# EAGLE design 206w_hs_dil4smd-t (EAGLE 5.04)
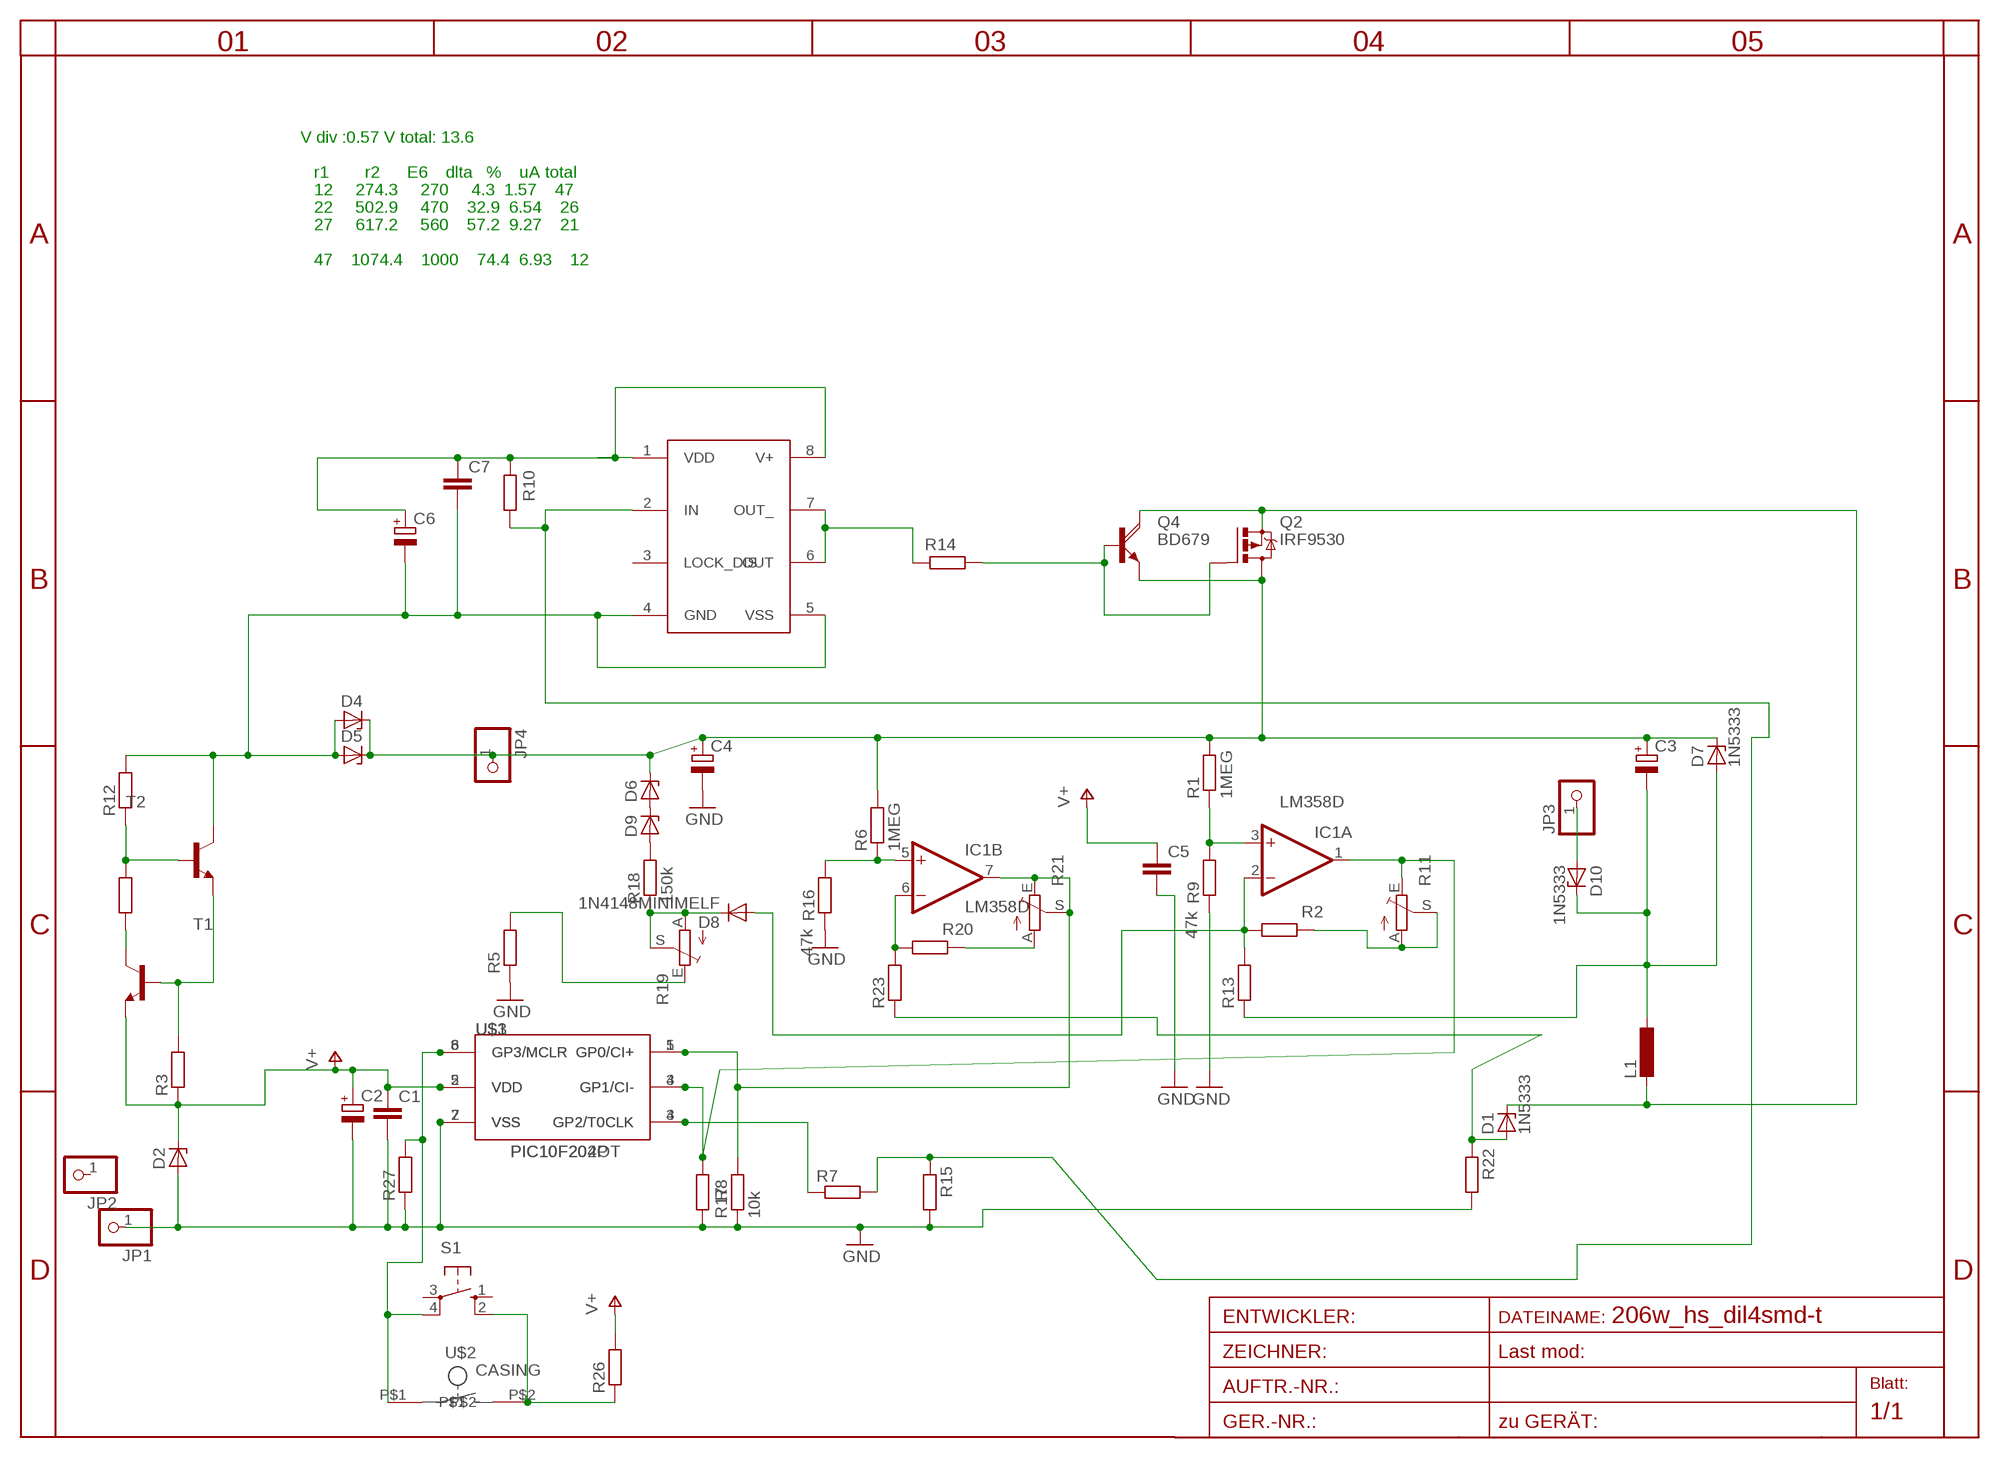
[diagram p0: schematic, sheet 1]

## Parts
C1  C-EUC1206  [C1206]
C2  CPOL-EUSANYO_SMD_E12  [SANYO-OSCON_SMD_E12]
C3  CPOL-EUE5-8.5  [E5-8,5]
C4  CPOL-EUE5-8.5  [E5-8,5]
C5  C-EUC1206  [C1206]
C6  CPOL-EUSANYO_SMD_E12  [SANYO-OSCON_SMD_E12]
C7  C-EUC1206  [C1206]
D1  1N5333  [C1702-15]
D2  ZENER-DIODESOT23  [SOT23]
D4  ZENER-DIODESMB  [SMB]
D5  ZENER-DIODESMB  [SMB]
D6  ZENER-DIODESMB  [SMB]
D7  1N5333  [C1702-15]
D8  1N4148MINIMELF  [MINIMELF]
D9  ZENER-DIODESMB  [SMB]
D10  1N5333  [C1702-15]
IC1  LM358D  [SO08]
IC3  TC4432X  [SO-08]
JP1  PINHD-1X1  [1X01]
JP2  PINHD-1X1  [1X01]
JP3  PINHD-1X1  [1X01]
JP4  PINHD-1X1  [1X01]
L1  L-EU2200-15.24  [2200-15.24]
Q2  IRF9530  [TO220BV]
Q4  BD679  [TO126AV]
R1  1MEG  R-EU_R1206  [R1206]
R2  R-EU_R0805  [R0805]
R3  R-EU_R0805  [R0805]
R5  R-EU_R0805  [R0805]
R6  1MEG  R-EU_R1206  [R1206]
R7  R-EU_R0805  [R0805]
R8  R-EU_R0805  [R0805]
R9  47k  R-EU_R0805  [R0805]
R10  R-EU_R0805  [R0805]
R11  TRIM_EU-CA6V  [CA6V]
R12  R-EU_R0805  [R0805]
R13  R-EU_R1206  [R1206]
R14  R-EU_0207/10  [0207/10]
R15  R-EU_R0805  [R0805]
R16  47k  R-EU_R0805  [R0805]
R17  10k  R-EU_R0805  [R0805]
R18  150k  R-EU_R1206  [R1206]
R19  TRIM_EU-CA6V  [CA6V]
R20  R-EU_R0805  [R0805]
R21  TRIM_EU-CA6V  [CA6V]
R22  R-EU_0309/12  [0309/12]
R23  R-EU_R1206  [R1206]
R24  R-EU_R0805  [R0805]
R26  R-EU_R0805  [R0805]
R27  R-EU_R0805  [R0805]
S1  10-XX  [B3F-10XX]
T1  BC846BLT1-NPN-SOT23-BEC  [SOT23-BEC]
T2  BC846BLT1-NPN-SOT23-BEC  [SOT23-BEC]
U$1  PIC10F202OT  [SOT23-6]
U$2  CASING  [CASING]
U$3  PIC10F204P  [DIL8]

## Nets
BB: IC3.2(IN) R7.2 R10.1 R15.1
EXIT: D10.A JP3.1
GND: C1.2 C2.- C4.- C5.2 D2.1(A) JP1.1 R5.1 R8.1 R9.1 R15.2 R16.1 R17.1 R22.2 R27.1 U$1.2(VSS) U$3.7(VSS)
HOT2: D1.A R22.1 R23.1
HOTSPOT: D1.C L1.2 Q4.C
N$1: R2.1 R11.A R11.S
N$2: IC1.1(A:OUT) R8.2 R11.E U$1.3(GP1/CI-) U$3.4(GP1/CI-)
N$3: R5.2 R19.E
N$4: D9.A R18.2
N$5: IC1.5(B:+IN) R6.1 R16.2
N$6: C6.- C7.2 D4.A D5.A IC3.4(GND) IC3.5(VSS) R12.2 T2.C
N$7: R27.2 S1.4(P1) U$1.6(GP3/MCLR) U$2.P$1 U$3.8(GP3/MCLR)
N$8: IC1.3(A:+IN) R1.1 R9.2
N$9: R7.1 U$1.4(GP2/T0CLK) U$3.3(GP2/T0CLK)
N$10: Q2.G Q4.B R14.1
N$11: IC3.6(OUT) IC3.7(OUT_) R14.2
N$12: R3.2 T1.B T2.E
N$13: D8.C R18.1 R19.A R19.S
N$14: IC1.7(B:OUT) R17.2 R21.E R21.S U$1.1(GP0/CI+) U$3.5(GP0/CI+)
N$15: D8.A IC1.2(A:-IN) R2.2 R13.2
N$17: R26.1 S1.2(S1) U$2.P$2
N$19: R24.1 T1.C
N$22: R12.1 R24.2 T2.B
N$23: D6.A D9.C
N$24: IC1.6(B:-IN) R20.2 R23.2
N$25: R20.1 R21.A
V60: C3.+ C4.+ D4.C D5.C D6.C D7.C JP4.1 Q2.D Q4.E R1.2 R6.2
V+: C1.1 C2.+ C5.1 D2.3(C) R3.1 R26.2 T1.E U$1.5(VDD) U$3.2(VDD)
VCC: C6.+ C7.1 IC3.1(VDD) IC3.8(V+) R10.2
VOUT: C3.- D7.A D10.C L1.1 R13.1
Unconnected: IC3.3(LOCK_DIS) JP2.1 Q2.S S1.1(S) S1.3(P)

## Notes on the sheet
- V div :0.57 V total: 13.6
- r1        r2      E6    dlta   %    uA total
- 12     274.3     270     4.3  1.57    47
- 22     502.9     470    32.9  6.54    26
- 27     617.2     560    57.2  9.27    21
- 47    1074.4    1000    74.4  6.93    12

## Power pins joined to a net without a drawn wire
GND: IC1.4(P:V-)
V+: IC1.8(P:V+)

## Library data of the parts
C1 C5 C7 = rcl:C-EU: CAPACITOR, European symbol
C2-C4 C6 = rcl:CPOL-EU: POLARIZED CAPACITOR, European symbol
D1 D7 D10 = diode-1:1N5333: Z DIODE
D2 D4-D6 D9 = diode-1:ZENER-DIODE: Z-Diode
D8 = diode-1:1N4148: DIODE
IC1 = linear4:LM358: OP AMP
IC3 = microchip:TC4432
JP1-JP4 = pinhead:PINHD-1X1: PIN HEADER
L1 = rcl:L-EU: INDUCTOR, European symbol
Q2 = transistor-power:IRF9530: P-CHANNEL HEXFET POWER-MOS-FET Source: http://www.irf.com/product-info/datasheets/data/irf9530.pdf
Q4 = transistor-power:BD679: NPN DARLINGTON TRANSISTOR
R1-R3 R5 R6 R8-R10 R12 R14-R16 R20 R24 R26 R27 = rcl:R-EU_: RESISTOR, European symbol
R7 R13 R17 R18 R22 R23 = rcl-2:R-EU_: RESISTOR, European symbol
R11 R19 R21 = pot:TRIM_EU-: POTENTIOMETER
S1 = switch-omron:10-XX: OMRON SWITCH
T1 T2 = transistor-neu-to92:*-NPN-: NPN Transistror
U$1 U$3 = microchip-5:PIC10F2*: uPC nW 0,25/0,5k Program Flash memory Comparator
U$2 = button:CASING

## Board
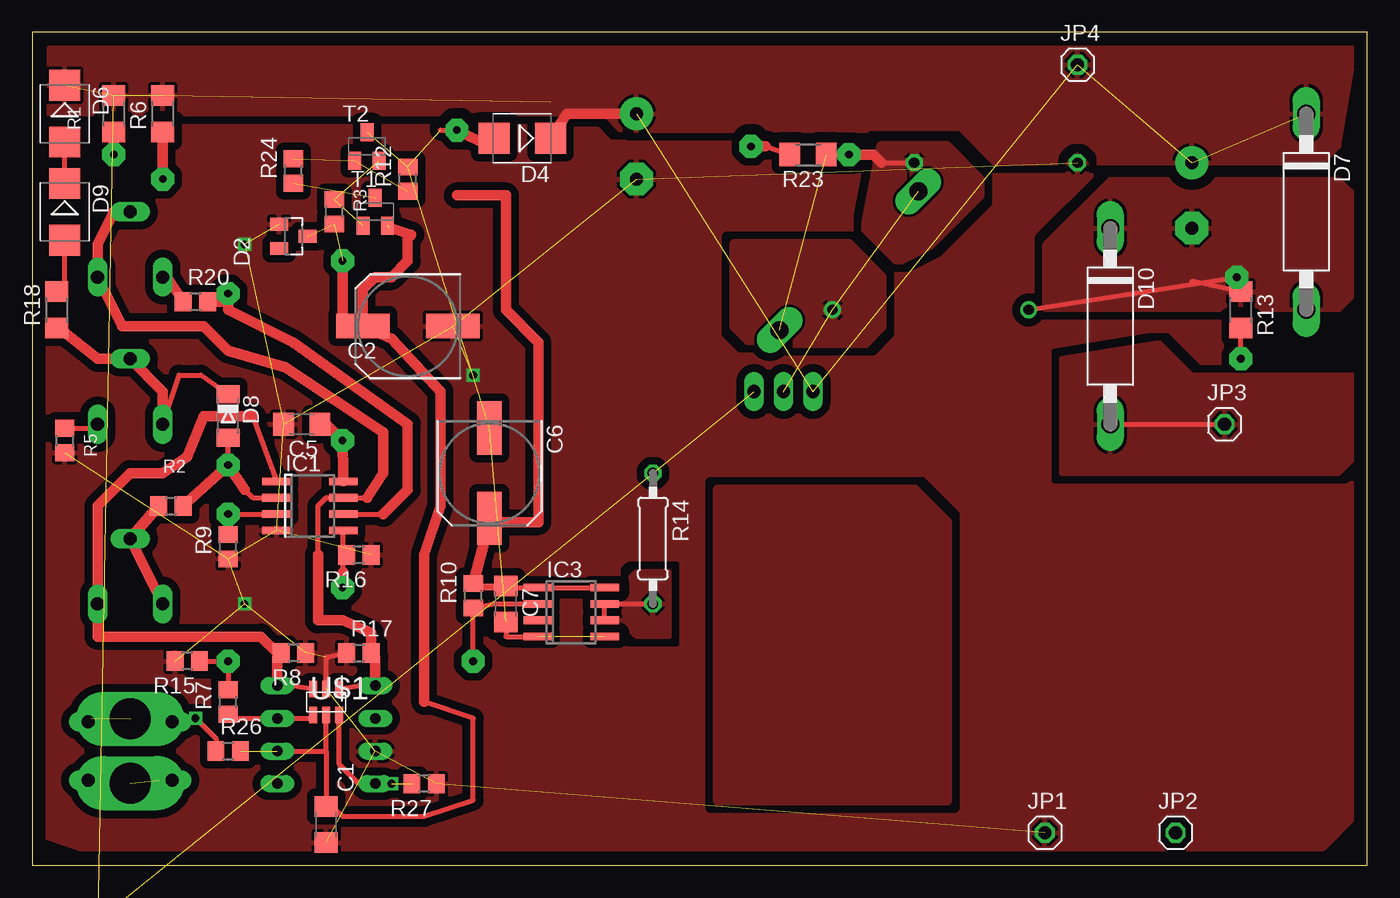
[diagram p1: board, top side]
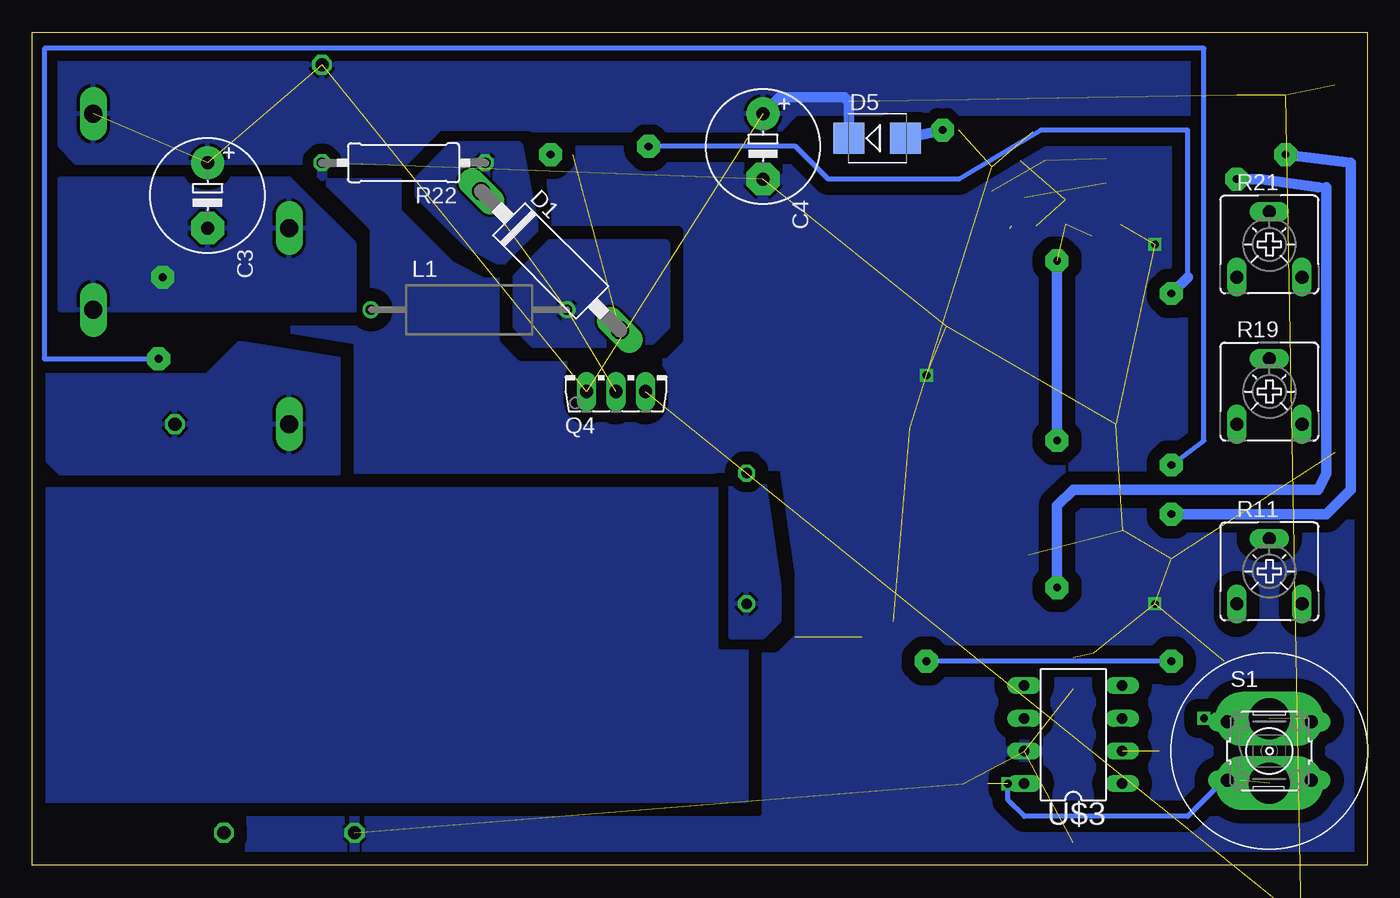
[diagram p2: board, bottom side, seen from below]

Size 103.81 x 64.76 mm. Coordinates in mm from the lower left corner, seen from the top.
Outline: 0,0 103.81,0 103.81,64.76 0,64.76 0,0
Copper layers (1*16): Top 0.035mm / dielectric 1.5mm / Bottom 0.035mm
Design rules "default": minimum track width 10mil, minimum drill 24mil, track to track 8mil, track to pad 8mil, pad to pad 8mil, via to via 8mil, smd to smd 8mil, copper to edge 40mil, drill to drill 8mil, minimum pad ring 10mil, minimum via ring 8mil, stop-mask expansion 4mil, vias tented up to drill 0mil, thermal gap 10mil

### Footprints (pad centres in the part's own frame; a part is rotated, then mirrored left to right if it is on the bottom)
C1206 = smd 1.6 x 1.8: 1 -1.4,0; 2 1.4,0
SANYO-OSCON_SMD_E12 = smd 4.15 x 1.9: + 3.5,0; - -3.5,0
E5-8,5 = drill 1.016 pad 2.54 round: + -2.54,0 | drill 1.016 pad 2.54 octagon: - 2.54,0
C1702-15 = drill 1.397 long: A 7.62,0; C -7.62,0
SOT23 = smd 1 x 1.4: 1 -0.95,-1.1; 2 0.95,-1.1; 3 0,1.1
SMB = smd 2.4 x 2.4: A 2.2,0; C -2.2,0
MINIMELF = smd 1.4 x 1.8: A 1.7,0; C -1.7,0
SO08 = smd 0.6 x 2.2: 1 -1.905,-2.6; 2 -0.635,-2.6; 3 0.635,-2.6; 4 1.905,-2.6; 5 1.905,2.6; 6 0.635,2.6; 7 -0.635,2.6; 8 -1.905,2.6
SO-08 = smd 0.6 x 2.2: 1 -1.905,-2.6; 2 -0.635,-2.6; 3 0.635,-2.6; 4 1.905,-2.6; 5 1.905,2.6; 6 0.635,2.6; 7 -0.635,2.6; 8 -1.905,2.6
1X01 = drill 1.016 octagon: 1 0,0
2200-15.24 = drill 0.8 pad 1.27 round: 1 -7.62,0; 2 7.62,0
TO220BV = drill 1.016 long: D 0,-2.54; G -2.54,-2.54; S 2.54,-2.54
TO126AV = drill 1.016 long: B 2.286,-1.27; C 0,-1.27; E -2.286,-1.27
R1206 = smd 1.6 x 1.803: 1 -1.422,0; 2 1.422,0
R0805 = smd 1.3 x 1.5: 1 -0.95,0; 2 0.95,0
CA6V = drill 1.016 long: A -2.54,-2.54; E 2.54,-2.54; S 0,2.54
0207/10 = drill 0.813 octagon: 1 -5.08,0; 2 5.08,0
0309/12 = drill 0.813 octagon: 1 -6.35,0; 2 6.35,0
B3F-10XX = drill 1.016 long: 1 -3.251,2.261; 2 3.251,2.261; 3 -3.251,-2.261; 4 3.251,-2.261
SOT23-BEC = smd 1 x 1.4: B -0.95,-1.1; C 0,1.1; E 0.95,-1.1
SOT23-6 = smd 0.635 x 1.27: 1 -1.016,-1.016; 2 0,-1.016; 3 1.016,-1.016; 4 1.016,1.016; 5 0,1.016; 6 -1.016,1.016
CASING = drill 3.2 pad 3.81 long: P$1 -2.5,0; P$2 2.5,0
DIL8 = drill 0.813 long: 1 -3.81,-3.81; 2 -1.27,-3.81; 3 1.27,-3.81; 4 3.81,-3.81; 5 3.81,3.81; 6 1.27,3.81; 7 -1.27,3.81; 8 -3.81,3.81

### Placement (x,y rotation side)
C1  22.86,3.17 270 top
C2  29.21,41.91 180 top
C3  90.17,52.07 270 bottom
C4  46.99,55.88 270 bottom
C5  20.95,34.29 180 top
C6  35.56,30.48 270 top
C7  36.83,20.32 270 top
D1  63.5,46.99 315 bottom
D2  20.32,48.9 270 top
D4  38.1,56.52 180 top
D5  38.1,56.52 0 bottom
D6  2.54,58.42 270 top
D7  99.06,50.8 270 top
D8  15.24,34.92 270 top
D9  2.54,50.8 270 top
D10  83.82,41.91 270 top
IC1  21.59,27.94 270 top
IC3  41.91,19.68 270 top
JP1  78.74,2.54 0 top
JP2  88.9,2.54 0 top
JP3  92.71,34.29 0 top
JP4  81.28,62.23 0 top
L1  69.85,43.18 0 bottom
Q2  not placed on the board
Q4  58.42,38.1 0 bottom
R1  6.35,58.42 90 top
R2  10.79,27.94 0 top
R3  23.5,50.8 90 top
R5  2.54,33.02 90 top
R6  10.16,58.42 90 top
R7  15.24,12.7 90 top
R8  20.32,16.51 180 top
R9  15.24,24.77 90 top
R10  34.29,20.95 90 top
R11  7.62,22.86 0 bottom
R12  29.21,53.34 90 top
R13  93.98,43.18 270 top
R14  48.26,25.4 270 top
R15  12.06,15.88 180 top
R16  25.4,24.13 180 top
R17  25.4,16.51 0 top
R18  1.91,43.18 90 top
R19  7.62,36.83 0 bottom
R20  12.7,43.81 0 top
R21  7.62,48.26 0 bottom
R22  74.93,54.61 180 bottom
R23  60.33,55.24 180 top
R24  20.32,53.98 90 top
R26  15.24,8.89 0 top
R27  30.48,6.35 180 top
S1  7.62,8.89 0 bottom
T1  26.67,50.8 0 top
T2  26.04,55.88 0 top
U$1  22.86,12.7 180 top
U$2  7.62,8.89 90 bottom
U$3  22.86,10.16 90 bottom

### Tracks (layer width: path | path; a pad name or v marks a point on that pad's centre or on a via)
BB  (via drill 0.6 pad 1.78)
  Top 0.406: IC3.2 35.88,20.32 R10.1 v34.29,15.88 | R7.2 v15.24,15.88 R15.1
  Bottom 0.406: v15.24,15.88 v34.29,15.88
EXIT
  Top 0.406: D10.A JP3.1
  pour Top: 80.01,39.37 80.01,30.48 101.6,30.48 102.87,31.75 102.87,38.1 90.17,38.1 87.63,40.64
  pour Bottom: 80.01,39.37 80.01,30.48 101.6,30.48 102.87,31.75 102.87,38.1 90.17,38.1 87.63,40.64
GND  (via drill 0.6)  (18 unrouted)
  Top 0.406: U$1.2 22.86,16.19 R17.1
  other vias: 16.51,48.26 16.51,20.32 34.29,38.1
  pour Bottom (isolate 1.016, rank 5): 102.87,60.96 102.87,0 90.17,0 1.27,1.27 1.27,53.34 1.27,58.42
  pour Top (isolate 0.61, rank 5): 1.27,63.5 99.06,63.5 102.87,59.69 102.87,3.81 100.33,1.27 3.81,1.27 0,2.54
HOT2  (via drill 0.6 pad 1.78)  (1 unrouted)
  Top 0.406: R23.1 v63.5,55.24 | 66.04,54.61 R22.1
  Top 0.813: v63.5,55.24 65.41,55.24 66.04,54.61
  pour Top (rank 2): 66.04,55.88 71.12,55.88 73.66,53.34 73.66,52.07 69.85,48.26 67.31,46.99 64.77,49.53
  pour Bottom (rank 2): 66.04,55.88 71.12,55.88 73.66,53.34 73.66,52.07 69.85,48.26 67.31,46.99 64.77,49.53
HOTSPOT  (2 unrouted)
  pour Top: 54.61,48.26 63.5,48.26 66.04,45.72 66.04,41.91 64.77,40.64 55.88,40.64 54.61,41.91
  pour Bottom: 54.61,48.26 63.5,48.26 66.04,45.72 66.04,41.91 64.77,40.64 55.88,40.64 54.61,41.91
N$1
  Top 0.813: R11.A R11.S R2.1
N$2
  Top 0.406: 17.14,34.92 IC1.1 | U$1.3 20.32,13.97 U$3.4 | 19.05,16.19 R8.2 19.05,16.51
  Top 0.813: 17.14,34.92 13.34,34.92 12.06,31.75 10.16,30.48 7.62,30.48 5.08,27.94 R11.E 5.08,17.78 17.78,17.78 19.05,16.51 | 19.05,16.19 U$3.4
N$3
  Top 0.406: R5.2 4.76,33.97 R19.E
N$4
  Top 0.406: D9.A 2.54,45.24 R18.2
N$5  (via drill 0.6 pad 1.78)
  Top 0.406: 24.19,24.39 R16.2 | 24.19,22.8 24.19,24.39 | 24.19,24.39 IC1.5
  Top 0.813: v10.16,53.34 R6.1 | v24.13,21.59 24.19,22.8
  Bottom 0.61: 3.17,52.7 3.81,52.7
  Bottom 0.813: v10.16,53.34 8.26,53.34 3.81,52.7 | 3.17,52.7 3.17,30.48 3.81,29.21 22.86,29.21 24.13,27.94 v24.13,21.59
N$6  (via drill 0.6 pad 1.78)  (5 unrouted)
  Top 0.406: C7.2 36.83,17.78 IC3.4 | 35.56,55.88 D5.A | 31.75,57.15 v33.02,57.15
  Top 0.813: v33.02,57.15 35.56,55.88
  Bottom 0.813: v33.02,57.15 D5.A
N$7  (via drill 0.6)  (2 unrouted)
  Top 0.406: U$1.6 23.88,7.87 25.4,6.35 U$3.8 v27.94,6.35
  Bottom 0.406: S1.4 9.88,6.63 10.16,6.35 11.43,6.35 13.97,3.81 26.67,3.81 27.94,5.08 v27.94,6.35
N$8  (via drill 0.6 pad 1.78)
  Top 0.406: IC1.3 15.56,27.3 R9.2 v15.24,27.3
  Top 0.813: v6.35,55.24 R1.1
  Bottom 0.813: v6.35,55.24 1.27,54.61 1.27,29.21 3.17,27.3 v15.24,27.3
N$9
  Top 0.406: R7.1 15.56,11.43 U$3.3 21.59,11.43 U$1.4
N$10  (2 unrouted)
N$11
  Top 0.406: R14.2 IC3.7 IC3.6
  pour Bottom (isolate 0.813): 45.72,21.59 46.99,30.48 49.53,30.48 49.53,17.78 46.99,17.78 45.72,19.05
  pour Top (isolate 0.813): 45.72,21.59 46.99,22.86 49.53,22.86 49.53,17.78 46.99,17.78 45.72,19.05
N$12  (2 unrouted)
N$13
  Top 0.406: R19.A 11.43,38.1 13.13,38.1 D8.C
  Top 0.813: R18.1 1.91,41.91 5.08,39.37 R19.S 10.16,36.83 R19.A
N$14
  Top 0.406: 26.04,28.57 IC1.7 22.86,28.57 22.23,27.94 22.23,24.13 | 26.67,16.19 R17.2 | U$1.1 25.4,13.97 U$3.5
  Top 0.813: 26.04,28.57 27.3,30.48 27.3,33.66 19.68,38.73 15.24,40.01 13.34,41.91 6.99,41.91 R21.E 5.08,48.26 6.35,50.8 R21.S | R17.2 26.35,18.1 24.13,19.05 22.23,19.05 22.23,24.13 | U$3.5 26.67,16.19
N$15  (via drill 0.6 pad 1.78)
  Top 0.406: 16.51,29.21 17.14,28.57 IC1.2 | v93.98,39.37 R13.2 | v15.24,31.11 D8.A
  Top 0.813: 16.51,29.21 v15.24,31.11 R2.2
  Bottom 0.406: v93.98,39.37 102.87,39.37 102.87,63.5 12.7,63.5 12.7,33.02 v15.24,31.11
N$17  (via drill 0.6)  (1 unrouted)
  Top 0.406: R26.1 14.29,9.84 v12.7,11.43
  Bottom 0.406: v12.7,11.43 4.65,11.43 S1.2
N$19  (1 unrouted)
N$20
  pour Top (isolate 0.813, rank 3): 53.34,29.21 68.58,29.21 71.12,26.67 71.12,5.08 53.34,5.08
  pour Bottom (isolate 0.813, rank 3): 48.26,29.21 102.87,29.21 102.87,5.08 48.26,5.08
N$22  (2 unrouted)
N$23
  Top 0.406: D9.C D6.A
N$24  (via drill 0.6 pad 1.78)
  Top 0.406: 57,55.88 R23.2 | IC1.6 27.3,27.3
  Top 0.813: v55.88,55.88 57,55.88 | 27.3,27.3 29.21,29.21 29.21,34.29 20.32,40.64 15.24,43.18 v15.24,44.45 14.61,43.81 R20.2
  Bottom 0.406: v55.88,55.88 44.45,55.88 41.91,53.34 31.75,53.34 25.4,57.15 13.97,57.15 13.97,45.72
  Bottom 0.813: v15.24,44.45 13.97,45.72
N$25
  Top 0.813: R21.A 10.48,45.72 R20.1
V60  (8 unrouted)
  Top 0.813: C4.+ 41.57,58.42 D5.C
  Bottom 0.813: D5.C 40.3,59.35 40.64,59.69 45.72,59.69 C4.+
  pour Top (isolate 0.813, rank 4): 102.87,63.5 1.27,63.5 1.27,58.42 44.45,58.42 45.72,57.15 71.12,57.15 73.66,54.61 100.33,54.61 101.6,55.88
  pour Bottom (isolate 0.813, rank 4): 102.87,63.5 1.27,63.5 1.27,48.26 7.62,48.26 7.62,54.61 6.35,55.88 6.35,57.15 7.62,58.42 44.45,58.42 45.72,57.15 71.12,57.15 73.66,54.61 100.33,54.61 101.6,55.88
V+  (via drill 0.6 pad 1.78)  (4 unrouted)
  Top 0.406: C2.+ 24.13,41.91 | IC1.8 24.13,29.91 | U$3.2 22.86,8.89 | 22.86,8.89 U$1.5 | 30.48,12.7 34.29,11.43 34.29,5.08 30.48,3.81 24.13,3.81 23.5,4.45 22.99,4.45 C1.1 22.86,8.89
  Top 0.813: 27.79,49.53 27.94,49.53 29.46,49.02 29.21,48.77 29.21,46.99 27.94,45.72 26.67,45.72 25.71,44.76 C2.+ 27.94,40.95 31.75,36.83 31.75,27.94 30.48,24.13 30.48,12.7 | IC1.8 24.19,30.42 v24.13,33.02 22.86,34.29 C5.1 | 24.13,41.91 v24.13,46.99
  Bottom 0.813: v24.13,46.99 v24.13,33.02
VCC
  Top 0.406: IC3.8 IC3.1 35.24,21.59 R10.2 34.29,21.72 C7.1 | 35.56,26.67 C6.+
  Top 0.813: R10.2 35.56,26.67 39.37,26.67 39.37,40.64 36.83,43.18 36.83,52.07 33.02,52.07
VOUT  (via drill 0.6 pad 1.78)
  Top 0.406: L1.1 v93.66,45.72 R13.1 90.17,45.4
  pour Top (isolate 0.813, rank 3): 101.6,53.34 102.87,52.07 102.87,44.45 101.6,43.18 78.74,43.18 78.74,48.26 83.82,53.34
  pour Bottom (isolate 0.813, rank 3): 101.6,53.34 102.87,52.07 102.87,44.45 101.6,43.18 78.74,43.18 78.74,48.26 83.82,53.34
